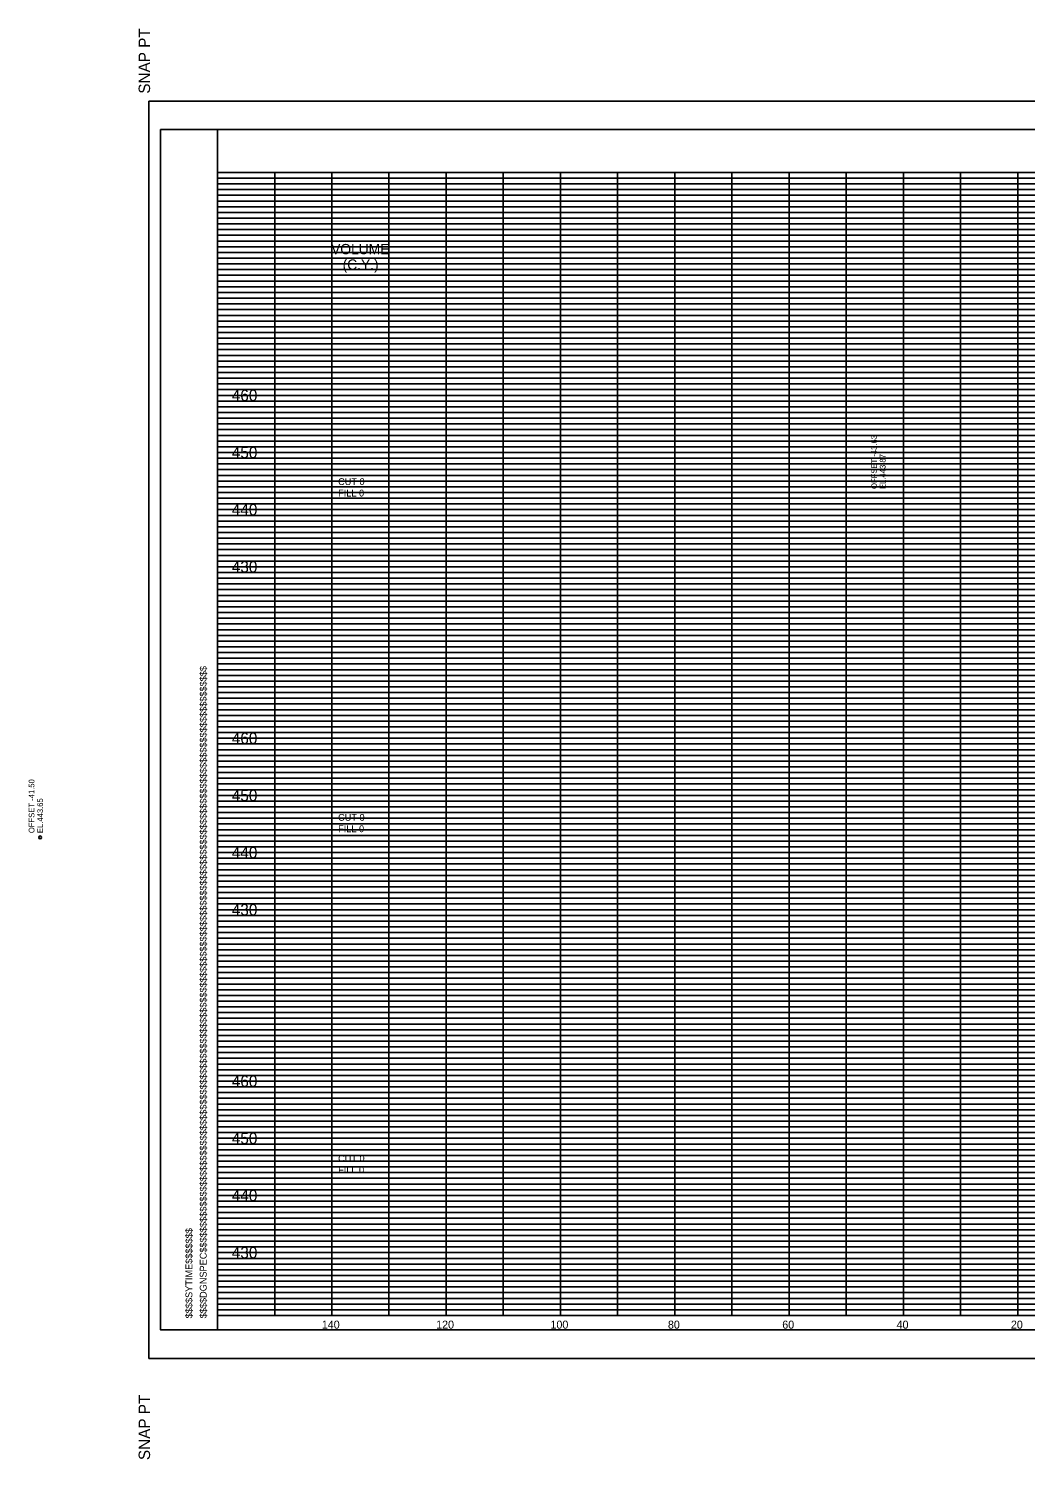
# Model space of a CAD drawing. Extents: x 967 to 1339, y 975 to 1507.
# Drawn here: x 967 to 1141.3, y 974.8 to 1225.2 of the extents above; entities that cross this region are included whole.
import ezdxf

# ---------------------------------------------------------------- set-up
doc = ezdxf.new("R2010")
doc.units = 0
for name, color, linetype in [('Default', 7, 'Continuous'), ('DESIGN - SCRATCH - User 1', 7, 'Continuous'), ('DESIGN - SHEET - Corner Text', 7, 'Continuous'), ('DESIGN - SHEET - Light Grid', 7, 'Continuous'), ('DESIGN - SHEET - Linework', 7, 'Continuous'), ('DESIGN - SHEET - Plot Shape', 7, 'Continuous'), ('DESIGN - TYPICAL - Slope Tie Point', 7, 'Continuous'), ('DESIGN - TYPICAL - Slope Tie Text', 7, 'Continuous'), ('DESIGN - TYPICAL - Text', 7, 'Continuous')]:
    doc.layers.add(name, color=color, linetype=linetype)

msp = doc.modelspace()

# ---------------------------------------------------------------- linework, layer by layer
at = {"layer": 'DESIGN - SCRATCH - User 1'}
msp.add_line((1000, 1000), (1000, 1000), dxfattribs=at)
at = {"layer": 'DESIGN - SHEET - Light Grid'}
for p, q in [((1000, 1199), (1280, 1199)), ((1000, 1198), (1280, 1198)), ((1000, 1197), (1320, 1197)), ((1000, 1196), (1320, 1196)), ((1000, 1195), (1320, 1195)), ((1000, 1194), (1320, 1194)), ((1000, 1193), (1320, 1193)), ((1000, 1192), (1320, 1192)), ((1000, 1191), (1320, 1191)), ((1000, 1189), (1320, 1189)), ((1000, 1188), (1320, 1188)), ((1000, 1187), (1320, 1187)), ((1000, 1186), (1320, 1186)), ((1000, 1185), (1320, 1185)), ((1000, 1184), (1320, 1184)), ((1000, 1183), (1320, 1183)), ((1000, 1182), (1320, 1182)), ((1000, 1181), (1320, 1181)), ((1000, 1179), (1320, 1179)), ((1000, 1178), (1320, 1178)), ((1000, 1177), (1320, 1177)), ((1000, 1176), (1320, 1176)), ((1000, 1175), (1320, 1175)), ((1000, 1174), (1320, 1174)), ((1000, 1173), (1320, 1173)), ((1000, 1172), (1320, 1172)), ((1000, 1171), (1320, 1171)), ((1000, 1169), (1320, 1169)), ((1000, 1168), (1320, 1168)), ((1000, 1167), (1320, 1167)), ((1000, 1166), (1320, 1166)), ((1000, 1165), (1320, 1165)), ((1000, 1164), (1320, 1164)), ((1000, 1163), (1320, 1163)), ((1000, 1162), (1320, 1162)), ((1000, 1161), (1320, 1161)), ((1000, 1159), (1320, 1159)), ((1000, 1158), (1320, 1158)), ((1000, 1157), (1320, 1157)), ((1000, 1156), (1320, 1156)), ((1000, 1155), (1320, 1155)), ((1000, 1154), (1320, 1154)), ((1000, 1153), (1320, 1153)), ((1000, 1152), (1320, 1152)), ((1000, 1151), (1320, 1151)), ((1000, 1149), (1320, 1149)), ((1000, 1148), (1320, 1148)), ((1000, 1147), (1320, 1147)), ((1000, 1146), (1320, 1146)), ((1000, 1145), (1320, 1145)), ((1000, 1144), (1320, 1144)), ((1000, 1143), (1320, 1143)), ((1000, 1142), (1320, 1142)), ((1000, 1141), (1320, 1141)), ((1000, 1139), (1320, 1139)), ((1000, 1138), (1320, 1138)), ((1000, 1137), (1320, 1137)), ((1000, 1136), (1320, 1136)), ((1000, 1135), (1320, 1135)), ((1000, 1134), (1320, 1134)), ((1000, 1133), (1320, 1133)), ((1000, 1132), (1320, 1132)), ((1000, 1131), (1320, 1131)), ((1000, 1129), (1320, 1129)), ((1000, 1128), (1320, 1128)), ((1000, 1127), (1320, 1127)), ((1000, 1126), (1320, 1126)), ((1000, 1125), (1320, 1125)), ((1000, 1124), (1320, 1124)), ((1000, 1123), (1320, 1123)), ((1000, 1122), (1320, 1122)), ((1000, 1121), (1320, 1121)), ((1000, 1119), (1320, 1119)), ((1000, 1118), (1320, 1118)), ((1000, 1117), (1320, 1117)), ((1000, 1116), (1320, 1116)), ((1000, 1115), (1320, 1115)), ((1000, 1114), (1320, 1114)), ((1000, 1113), (1320, 1113)), ((1000, 1112), (1320, 1112)), ((1000, 1111), (1320, 1111)), ((1000, 1109), (1320, 1109)), ((1000, 1108), (1320, 1108)), ((1000, 1107), (1320, 1107)), ((1000, 1106), (1320, 1106)), ((1000, 1105), (1320, 1105)), ((1000, 1104), (1320, 1104)), ((1000, 1103), (1320, 1103)), ((1000, 1102), (1320, 1102)), ((1000, 1101), (1320, 1101)), ((1000, 1099), (1320, 1099)), ((1000, 1098), (1320, 1098)), ((1000, 1097), (1320, 1097)), ((1000, 1096), (1320, 1096)), ((1000, 1095), (1320, 1095)), ((1000, 1094), (1320, 1094)), ((1000, 1093), (1320, 1093)), ((1000, 1092), (1320, 1092)), ((1000, 1091), (1320, 1091)), ((1000, 1089), (1320, 1089)), ((1000, 1088), (1320, 1088)), ((1000, 1087), (1320, 1087)), ((1000, 1086), (1320, 1086)), ((1000, 1085), (1320, 1085)), ((1000, 1084), (1320, 1084)), ((1000, 1083), (1320, 1083)), ((1000, 1082), (1320, 1082)), ((1000, 1081), (1320, 1081)), ((1000, 1079), (1320, 1079)), ((1000, 1078), (1320, 1078)), ((1000, 1077), (1320, 1077)), ((1000, 1076), (1320, 1076)), ((1000, 1075), (1320, 1075)), ((1000, 1074), (1320, 1074)), ((1000, 1073), (1320, 1073)), ((1000, 1072), (1320, 1072)), ((1000, 1071), (1320, 1071)), ((1000, 1069), (1320, 1069)), ((1000, 1068), (1320, 1068)), ((1000, 1067), (1320, 1067)), ((1000, 1066), (1320, 1066)), ((1000, 1065), (1320, 1065)), ((1000, 1064), (1320, 1064)), ((1000, 1063), (1320, 1063)), ((1000, 1062), (1320, 1062)), ((1000, 1061), (1320, 1061)), ((1000, 1059), (1320, 1059)), ((1000, 1058), (1320, 1058)), ((1000, 1057), (1320, 1057)), ((1000, 1056), (1320, 1056)), ((1000, 1055), (1320, 1055)), ((1000, 1054), (1320, 1054)), ((1000, 1053), (1320, 1053)), ((1000, 1052), (1320, 1052)), ((1000, 1051), (1320, 1051)), ((1000, 1049), (1320, 1049)), ((1000, 1048), (1320, 1048)), ((1000, 1047), (1320, 1047)), ((1000, 1046), (1320, 1046)), ((1000, 1045), (1320, 1045)), ((1000, 1044), (1320, 1044)), ((1000, 1043), (1320, 1043)), ((1000, 1042), (1320, 1042)), ((1000, 1041), (1320, 1041)), ((1000, 1039), (1320, 1039)), ((1000, 1038), (1320, 1038)), ((1000, 1037), (1320, 1037)), ((1000, 1036), (1320, 1036)), ((1000, 1035), (1320, 1035)), ((1000, 1034), (1320, 1034)), ((1000, 1033), (1320, 1033)), ((1000, 1032), (1320, 1032)), ((1000, 1031), (1320, 1031)), ((1000, 1029), (1320, 1029)), ((1000, 1028), (1320, 1028)), ((1000, 1027), (1320, 1027)), ((1000, 1026), (1320, 1026)), ((1000, 1025), (1320, 1025)), ((1000, 1024), (1320, 1024)), ((1000, 1023), (1320, 1023)), ((1000, 1022), (1320, 1022)), ((1000, 1021), (1320, 1021)), ((1000, 1019), (1320, 1019)), ((1000, 1018), (1320, 1018)), ((1000, 1017), (1320, 1017)), ((1000, 1016), (1320, 1016)), ((1000, 1015), (1320, 1015)), ((1000, 1014), (1320, 1014)), ((1000, 1013), (1320, 1013)), ((1000, 1012), (1320, 1012)), ((1000, 1011), (1320, 1011)), ((1000, 1009), (1320, 1009)), ((1000, 1008), (1320, 1008)), ((1000, 1007), (1320, 1007)), ((1000, 1006), (1320, 1006)), ((1000, 1005), (1320, 1005)), ((1000, 1004), (1320, 1004)), ((1000, 1003), (1320, 1003)), ((1000, 1002), (1320, 1002)), ((1000, 1001), (1320, 1001))]:
    msp.add_line(p, q, dxfattribs=at)
at = {"layer": 'DESIGN - SHEET - Linework'}
for p, q in [((1000, 1200), (1320, 1200)), ((1010, 1000), (1010, 1200)), ((1020, 1000), (1020, 1200)), ((1030, 1000), (1030, 1200)), ((1040, 1000), (1040, 1200)), ((1050, 1000), (1050, 1200)), ((1060, 1000), (1060, 1200)), ((1070, 1000), (1070, 1200)), ((1080, 1000), (1080, 1200)), ((1090, 1000), (1090, 1200)), ((1100, 1000), (1100, 1200)), ((1110, 1000), (1110, 1200)), ((1120, 1000), (1120, 1200)), ((1130, 1000), (1130, 1200)), ((1140, 1000), (1140, 1200)), ((1000, 1190), (1320, 1190)), ((1000, 1180), (1320, 1180)), ((1000, 1170), (1320, 1170)), ((1000, 1160), (1320, 1160)), ((1000, 1150), (1320, 1150)), ((1000, 1140), (1320, 1140)), ((1000, 1130), (1320, 1130)), ((1000, 1120), (1320, 1120)), ((1000, 1110), (1320, 1110)), ((1000, 1100), (1320, 1100)), ((1000, 1090), (1320, 1090)), ((1000, 1080), (1320, 1080)), ((1000, 1070), (1320, 1070)), ((1000, 1060), (1320, 1060)), ((1000, 1050), (1320, 1050)), ((1000, 1040), (1320, 1040)), ((1000, 1030), (1320, 1030)), ((1000, 1020), (1320, 1020)), ((1000, 1010), (1320, 1010)), ((1000, 1000), (1320, 1000))]:
    msp.add_line(p, q, dxfattribs=at)
for points in [[(988, 1212.5), (1328, 1212.5), (1328, 992.5), (988, 992.5)], [(1000, 1207.5), (1320, 1207.5), (1320, 997.5), (1000, 997.5)]]:
    msp.add_lwpolyline(points, close=True, dxfattribs=at)
at = {"layer": 'DESIGN - SHEET - Plot Shape'}
msp.add_lwpolyline([(990, 1207.5), (1320, 1207.5), (1320, 997.5), (990, 997.5)], close=True, dxfattribs=at)
at = {"layer": 'DESIGN - TYPICAL - Slope Tie Point'}
msp.add_circle((968.97, 1083.65), 0.25, dxfattribs=at)

# ---------------------------------------------------------------- texts
at = {"layer": 'Default'}
for s, height, p in [('     460     ', 2, (998.79, 1160)), ('     450     ', 2, (998.79, 1150)), ('     440     ', 2, (998.79, 1140)), ('     430     ', 2, (998.79, 1130)), ('     460     ', 2, (998.79, 1100)), ('     450     ', 2, (998.79, 1090)), ('     440     ', 2, (998.79, 1080)), ('     430     ', 2, (998.79, 1070)), ('     460     ', 2, (998.79, 1040)), ('     450     ', 2, (998.79, 1030)), ('     440     ', 2, (998.79, 1020)), ('     430     ', 2, (998.79, 1010)), ('     140     ', 1.4, (1015.65, 997.7)), ('     120     ', 1.4, (1035.65, 997.7)), ('     100     ', 1.4, (1055.65, 997.7)), ('     80     ', 1.4, (1076.2, 997.7)), ('     60     ', 1.4, (1096.2, 997.7)), ('     40     ', 1.4, (1116.2, 997.7)), ('     20     ', 1.4, (1136.2, 997.7))]:
    msp.add_text(s, height=height, dxfattribs=at).set_placement(p)
at = {"layer": 'DESIGN - SHEET - Corner Text'}
for s, height, p in [('  SNAP PT', 2, (988.2, 1212.3)), ('$$$$DGNSPEC$$$$$$$$$$$$$$$$$$$$$$$$$$$$$$$$$$$$$$$$$$$$$$$$$$$$$$$$$$$$$$$$$$$$$$$$$$$$$$$$$$$$$$$$$$$$$$$$$$$$$$$$$$$$$$$$$$$', 1.2, (998.1, 999.5)), ('$$$$SYTIME$$$$$$$', 1.2, (995.6, 999.5)), ('SNAP PT  ', 2, (988.2, 974.7))]:
    msp.add_text(s, height=height, rotation=90, dxfattribs=at).set_placement(p)
at = {"layer": 'DESIGN - TYPICAL - Slope Tie Text'}
for s, p in [('OFFSET -43.63', (1115.37, 1144.62)), ('EL.443.87', (1116.87, 1144.62)), ('OFFSET -41.50', (967.97, 1084.4)), ('EL.443.65', (969.47, 1084.4))]:
    msp.add_text(s, height=1, rotation=90, dxfattribs=at).set_placement(p)
at = {"layer": 'DESIGN - TYPICAL - Text'}
for s, height, p in [('VOLUME', 1.8, (1019.89, 1185.69)), ('   (C.Y.)', 1.8, (1019.89, 1182.99)), ('CUT 0', 1.2, (1021.1, 1145.3)), ('FILL 0', 1.2, (1021.1, 1143.3)), ('CUT 0', 1.2, (1021.1, 1086.56)), ('FILL 0', 1.2, (1021.1, 1084.56)), ('CUT 0', 1.2, (1021.1, 1026.88)), ('FILL 0', 1.2, (1021.1, 1024.88))]:
    msp.add_text(s, height=height, dxfattribs=at).set_placement(p)

doc.saveas('drawing.dxf')
